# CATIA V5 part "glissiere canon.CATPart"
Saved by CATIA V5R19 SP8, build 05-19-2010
Part number: glissière canon 
Bounding box of the stored display mesh (mm): x 0 to 17.9, y -25.757 to -0.47, z 0 to 18.97
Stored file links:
  E:\Catia parts\GLOCK\Poignée\glissiere canon.CATPart
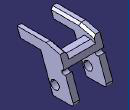
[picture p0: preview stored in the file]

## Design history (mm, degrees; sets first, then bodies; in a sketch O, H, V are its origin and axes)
Body1 (main body)
  Solid1: solid without history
